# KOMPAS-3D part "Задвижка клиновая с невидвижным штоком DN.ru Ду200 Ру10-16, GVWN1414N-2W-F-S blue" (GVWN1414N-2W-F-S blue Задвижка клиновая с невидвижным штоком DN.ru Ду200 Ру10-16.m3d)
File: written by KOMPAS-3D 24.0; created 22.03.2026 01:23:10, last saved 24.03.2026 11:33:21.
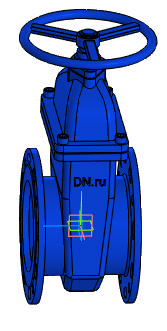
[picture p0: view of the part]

Document properties: Автор: R2D2; Полное имя файла: E:\Работа\Зайцев\!готово\GVWN1414N-2W-F-S blue Задвижка клиновая с невидвижным штоком DN.ru Ду40-300 Ру10-16\DN200\GVWN1414N-2W-F-S blue Задвижка клиновая с невидвижным штоком DN.ru Ду200 Ру10-16.m3d

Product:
- Part/product: Задвижка клиновая с невидвижным штоком DN.ru Ду200 Ру10-16  | designation GVWN1414N-2W-F-S blue
    Масса: 38
    Раздел спецификации: Прочие изделия
    Примечание: D040-10585

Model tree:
1. Операция без истории:1
2. Скругление:1  (with: Ребро.Операция без истории:1)
     Радиус = 5

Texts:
  GVWN1414N-2W-F-S blue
